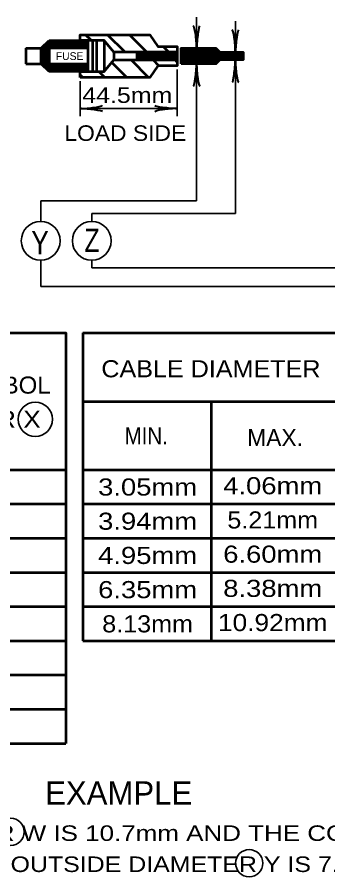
# Model space of a CAD drawing. Extents: x -32 to 824, y -6 to 538.
# Drawn here: x 393.4 to 441.4, y 267.8 to 400.5 of the extents above; entities that cross this region are included whole.
import ezdxf
from ezdxf.enums import TextEntityAlignment as Align

# ---------------------------------------------------------------- set-up
doc = ezdxf.new("R2010")
doc.units = 0
doc.header["$LTSCALE"] = 1.1
doc.layers.add('1', color=7, linetype='Continuous', lineweight=53)

msp = doc.modelspace()

# ---------------------------------------------------------------- linework, layer by layer
at = {"layer": '1', "lineweight": 35}
for p, q in [((421.085, 395.718), (421.085, 400.518)), ((427.085, 395.118), (427.085, 399.918)), ((421.085, 393.318), (421.085, 372.168)), ((427.085, 393.918), (427.085, 370.218)), ((418.085, 392.418), (418.085, 385.218)), ((403.085, 390.618), (403.085, 385.218)), ((403.085, 386.418), (418.085, 386.418)), ((421.085, 372.168), (396.989, 372.168)), ((396.989, 372.168), (396.989, 369.001)), ((427.085, 370.218), (404.885, 370.218)), ((404.885, 370.218), (404.885, 369.001)), ((396.989, 363.001), (396.989, 358.968)), ((404.885, 363.001), (404.885, 361.818)), ((404.885, 361.818), (511.085, 361.818)), ((396.989, 358.968), (448.542, 358.968))]:
    msp.add_line(p, q, dxfattribs=at)
at = {"layer": '1'}
for p, q in [((397.085, 395.718), (398.285, 396.918)), ((397.085, 395.687), (398.317, 396.918)), ((397.085, 395.517), (398.486, 396.918)), ((397.085, 395.347), (398.656, 396.918)), ((397.085, 395.178), (398.826, 396.918)), ((397.085, 395.008), (398.995, 396.918)), ((397.085, 394.838), (399.165, 396.918)), ((397.085, 394.668), (399.335, 396.918)), ((399.318, 395.718), (398.202, 396.834)), ((398.285, 396.918), (403.085, 396.918)), ((399.487, 395.718), (398.287, 396.918)), ((398.305, 395.718), (399.505, 396.918)), ((399.657, 395.718), (398.457, 396.918)), ((398.474, 395.718), (399.674, 396.918)), ((399.827, 395.718), (398.627, 396.918)), ((398.644, 395.718), (399.844, 396.918)), ((399.997, 395.718), (398.797, 396.918)), ((398.814, 395.718), (400.014, 396.918)), ((400.166, 395.718), (398.966, 396.918)), ((398.983, 395.718), (400.183, 396.918)), ((400.336, 395.718), (399.136, 396.918)), ((399.153, 395.718), (400.353, 396.918)), ((400.506, 395.718), (399.306, 396.918)), ((399.323, 395.718), (400.523, 396.918)), ((400.675, 395.718), (399.475, 396.918)), ((399.493, 395.718), (400.692, 396.918)), ((400.845, 395.718), (399.645, 396.918)), ((399.662, 395.718), (400.862, 396.918)), ((401.015, 395.718), (399.815, 396.918)), ((399.832, 395.718), (401.032, 396.918)), ((401.185, 395.718), (399.985, 396.918)), ((400.002, 395.718), (401.202, 396.918)), ((401.354, 395.718), (400.154, 396.918)), ((400.171, 395.718), (401.371, 396.918)), ((401.524, 395.718), (400.324, 396.918)), ((400.341, 395.718), (401.541, 396.918)), ((401.694, 395.718), (400.494, 396.918)), ((400.511, 395.718), (401.711, 396.918)), ((401.863, 395.718), (400.663, 396.918)), ((400.68, 395.718), (401.88, 396.918)), ((402.033, 395.718), (400.833, 396.918)), ((400.85, 395.718), (402.05, 396.918)), ((402.203, 395.718), (401.003, 396.918)), ((401.02, 395.718), (402.22, 396.918)), ((402.372, 395.718), (401.172, 396.918)), ((401.19, 395.718), (402.389, 396.918)), ((402.542, 395.718), (401.342, 396.918)), ((401.359, 395.718), (402.559, 396.918)), ((402.712, 395.718), (401.512, 396.918)), ((401.529, 395.718), (402.729, 396.918)), ((402.882, 395.718), (401.682, 396.918)), ((401.699, 395.718), (402.899, 396.918)), ((403.051, 395.718), (401.851, 396.918)), ((401.868, 395.718), (403.068, 396.918)), ((403.221, 395.718), (402.021, 396.918)), ((402.038, 395.718), (403.238, 396.918)), ((403.391, 395.718), (402.191, 396.918)), ((402.208, 395.718), (403.408, 396.918)), ((403.56, 395.718), (402.36, 396.918)), ((402.377, 395.718), (403.577, 396.918)), ((403.73, 395.718), (402.53, 396.918)), ((402.547, 395.718), (403.747, 396.918)), ((403.9, 395.718), (402.7, 396.918)), ((402.717, 395.718), (403.917, 396.918)), ((404.069, 395.718), (402.869, 396.918)), ((402.887, 395.718), (404.087, 396.918)), ((404.239, 395.718), (403.039, 396.918)), ((403.056, 395.718), (404.256, 396.918)), ((404.285, 395.841), (403.209, 396.918)), ((403.226, 395.718), (404.285, 396.777)), ((404.285, 396.011), (403.379, 396.918)), ((404.285, 396.181), (403.548, 396.918)), ((404.285, 396.351), (403.718, 396.918)), ((404.285, 396.52), (403.888, 396.918)), ((404.83, 396.918), (403.93, 397.818)), ((404.285, 396.69), (404.057, 396.918)), ((404.285, 396.86), (404.227, 396.918)), ((405.005, 396.918), (405.005, 392.118)), ((405.605, 396.918), (405.605, 392.118)), ((406.805, 396.918), (406.805, 392.118)), ((410.024, 395.118), (407.324, 397.818)), ((413.418, 395.118), (410.719, 397.818)), ((394.685, 395.718), (394.685, 393.318)), ((394.685, 395.718), (397.085, 395.718)), ((397.085, 394.499), (398.285, 395.699)), ((398.285, 394.374), (397.085, 395.574)), ((397.085, 394.329), (398.285, 395.529)), ((398.285, 394.544), (397.099, 395.731)), ((398.285, 394.714), (397.183, 395.816)), ((398.285, 394.883), (397.268, 395.901)), ((398.285, 395.053), (397.353, 395.986)), ((398.285, 395.223), (397.438, 396.07)), ((398.285, 395.393), (397.523, 396.155)), ((398.285, 395.562), (397.608, 396.24)), ((398.3, 395.718), (397.692, 396.325)), ((398.469, 395.718), (397.777, 396.41)), ((398.639, 395.718), (397.862, 396.495)), ((398.809, 395.718), (397.947, 396.579)), ((398.978, 395.718), (398.032, 396.664)), ((399.148, 395.718), (398.117, 396.749)), ((403.396, 395.718), (404.285, 396.608)), ((403.565, 395.718), (404.285, 396.438)), ((403.735, 395.718), (404.285, 396.268)), ((403.905, 395.718), (404.285, 396.099)), ((404.075, 395.718), (404.285, 395.929)), ((404.244, 395.718), (404.285, 395.759)), ((404.285, 395.718), (404.285, 393.318)), ((416.813, 395.118), (415.913, 396.018)), ((418.685, 395.591), (418.813, 395.718)), ((418.685, 395.421), (418.983, 395.718)), ((418.685, 395.251), (419.152, 395.718)), ((418.685, 395.081), (419.322, 395.718)), ((418.685, 394.912), (419.492, 395.718)), ((418.685, 394.742), (419.661, 395.718)), ((418.685, 394.572), (419.831, 395.718)), ((418.685, 394.403), (420.001, 395.718)), ((418.685, 394.233), (420.171, 395.718)), ((418.685, 394.063), (420.34, 395.718)), ((418.685, 393.893), (420.51, 395.718)), ((418.685, 393.724), (420.68, 395.718)), ((418.685, 393.554), (420.849, 395.718)), ((418.685, 393.384), (421.019, 395.718)), ((420.933, 393.318), (418.685, 395.565)), ((421.103, 393.318), (418.703, 395.718)), ((418.789, 393.318), (421.189, 395.718)), ((421.272, 393.318), (418.872, 395.718)), ((418.958, 393.318), (421.358, 395.718)), ((421.442, 393.318), (419.042, 395.718)), ((419.128, 393.318), (421.528, 395.718)), ((421.612, 393.318), (419.212, 395.718)), ((419.298, 393.318), (421.698, 395.718)), ((421.781, 393.318), (419.381, 395.718)), ((419.468, 393.318), (421.868, 395.718)), ((421.951, 393.318), (419.551, 395.718)), ((419.637, 393.318), (422.037, 395.718)), ((422.121, 393.318), (419.721, 395.718)), ((419.807, 393.318), (422.207, 395.718)), ((422.29, 393.318), (419.89, 395.718)), ((419.977, 393.318), (422.377, 395.718)), ((422.46, 393.318), (420.06, 395.718)), ((420.146, 393.318), (422.546, 395.718)), ((422.63, 393.318), (420.23, 395.718)), ((420.316, 393.318), (422.716, 395.718)), ((422.8, 393.318), (420.4, 395.718)), ((420.486, 393.318), (422.886, 395.718)), ((422.969, 393.318), (420.569, 395.718)), ((420.656, 393.318), (423.055, 395.718)), ((423.139, 393.318), (420.739, 395.718)), ((420.825, 393.318), (423.225, 395.718)), ((423.309, 393.318), (420.909, 395.718)), ((420.995, 393.318), (423.395, 395.718)), ((423.478, 393.318), (421.078, 395.718)), ((421.165, 393.318), (423.565, 395.718)), ((423.648, 393.318), (421.248, 395.718)), ((421.334, 393.318), (423.734, 395.718)), ((423.818, 393.318), (421.418, 395.718)), ((421.504, 393.318), (423.904, 395.718)), ((423.988, 393.318), (421.588, 395.718)), ((421.674, 393.318), (424.074, 395.718)), ((424.121, 393.354), (421.757, 395.718)), ((421.843, 393.318), (424.164, 395.639)), ((424.206, 393.439), (421.927, 395.718)), ((422.013, 393.318), (424.249, 395.554)), ((424.291, 393.524), (422.097, 395.718)), ((422.183, 393.318), (424.334, 395.469)), ((424.376, 393.608), (422.266, 395.718)), ((424.461, 393.693), (422.436, 395.718)), ((424.546, 393.778), (422.606, 395.718)), ((424.63, 393.863), (422.775, 395.718)), ((424.745, 393.918), (422.945, 395.718)), ((424.915, 393.918), (423.115, 395.718)), ((425.085, 393.918), (423.285, 395.718)), ((425.254, 393.918), (423.454, 395.718)), ((425.424, 393.918), (423.624, 395.718)), ((425.594, 393.918), (423.794, 395.718)), ((425.763, 393.918), (423.963, 395.718)), ((398.285, 394.205), (397.085, 395.405)), ((397.085, 394.159), (398.285, 395.359)), ((398.285, 394.035), (397.085, 395.235)), ((397.085, 393.99), (398.285, 395.19)), ((398.285, 393.865), (397.085, 395.065)), ((397.085, 393.82), (398.285, 395.02)), ((398.285, 393.696), (397.085, 394.896)), ((397.085, 393.65), (398.285, 394.85)), ((398.285, 393.526), (397.085, 394.726)), ((397.085, 393.481), (398.285, 394.681)), ((398.285, 393.356), (397.085, 394.556)), ((399.354, 392.118), (397.085, 394.386)), ((399.184, 392.118), (397.085, 394.217)), ((397.089, 393.314), (398.285, 394.511)), ((397.174, 393.23), (398.285, 394.341)), ((397.259, 393.145), (398.285, 394.171)), ((408.305, 395.118), (408.305, 393.918)), ((411.905, 394.992), (412.031, 395.118)), ((411.905, 394.822), (412.201, 395.118)), ((411.905, 394.653), (412.371, 395.118)), ((411.905, 394.483), (412.541, 395.118)), ((411.905, 394.313), (412.71, 395.118)), ((411.905, 394.143), (412.88, 395.118)), ((411.905, 393.974), (413.05, 395.118)), ((412.946, 393.918), (411.905, 394.958)), ((412.776, 393.918), (411.905, 394.788)), ((412.606, 393.918), (411.905, 394.619)), ((412.437, 393.918), (411.905, 394.449)), ((412.267, 393.918), (411.905, 394.279)), ((412.097, 393.918), (411.905, 394.11)), ((413.115, 393.918), (411.915, 395.118)), ((412.019, 393.918), (413.219, 395.118)), ((413.285, 393.918), (412.085, 395.118)), ((412.189, 393.918), (413.389, 395.118)), ((413.455, 393.918), (412.255, 395.118)), ((412.359, 393.918), (413.559, 395.118)), ((413.625, 393.918), (412.425, 395.118)), ((412.529, 393.918), (413.728, 395.118)), ((413.794, 393.918), (412.594, 395.118)), ((412.698, 393.918), (413.898, 395.118)), ((413.964, 393.918), (412.764, 395.118)), ((412.868, 393.918), (414.068, 395.118)), ((414.134, 393.918), (412.934, 395.118)), ((413.038, 393.918), (414.238, 395.118)), ((414.303, 393.918), (413.103, 395.118)), ((413.207, 393.918), (414.407, 395.118)), ((414.473, 393.918), (413.273, 395.118)), ((413.377, 393.918), (414.577, 395.118)), ((414.643, 393.918), (413.443, 395.118)), ((413.547, 393.918), (414.747, 395.118)), ((414.812, 393.918), (413.612, 395.118)), ((413.716, 393.918), (414.916, 395.118)), ((414.982, 393.918), (413.782, 395.118)), ((413.886, 393.918), (415.086, 395.118)), ((415.152, 393.918), (413.952, 395.118)), ((414.056, 393.918), (415.256, 395.118)), ((415.322, 393.918), (414.122, 395.118)), ((414.226, 393.918), (415.425, 395.118)), ((415.491, 393.918), (414.291, 395.118)), ((414.395, 393.918), (415.595, 395.118)), ((415.661, 393.918), (414.461, 395.118)), ((414.565, 393.918), (415.765, 395.118)), ((415.831, 393.918), (414.631, 395.118)), ((414.735, 393.918), (415.935, 395.118)), ((416, 393.918), (414.8, 395.118)), ((414.904, 393.918), (416.104, 395.118)), ((416.17, 393.918), (414.97, 395.118)), ((415.074, 393.918), (416.274, 395.118)), ((416.34, 393.918), (415.14, 395.118)), ((415.244, 393.918), (416.444, 395.118)), ((416.51, 393.918), (415.31, 395.118)), ((415.413, 393.918), (416.614, 395.118)), ((416.679, 393.918), (415.479, 395.118)), ((415.583, 393.918), (416.783, 395.118)), ((416.849, 393.918), (415.649, 395.118)), ((415.753, 393.918), (416.953, 395.118)), ((417.019, 393.918), (415.819, 395.118)), ((415.923, 393.918), (417.123, 395.118)), ((417.188, 393.918), (415.988, 395.118)), ((416.092, 393.918), (417.292, 395.118)), ((417.358, 393.918), (416.158, 395.118)), ((416.262, 393.918), (417.462, 395.118)), ((417.528, 393.918), (416.328, 395.118)), ((416.432, 393.918), (417.632, 395.118)), ((417.697, 393.918), (416.497, 395.118)), ((416.601, 393.918), (417.801, 395.118)), ((417.867, 393.918), (416.667, 395.118)), ((416.771, 393.918), (417.971, 395.118)), ((418.037, 393.918), (416.837, 395.118)), ((416.941, 393.918), (418.085, 395.062)), ((418.085, 394.039), (417.007, 395.118)), ((417.111, 393.918), (418.085, 394.893)), ((418.085, 394.209), (417.176, 395.118)), ((417.28, 393.918), (418.085, 394.723)), ((418.085, 394.379), (417.346, 395.118)), ((417.45, 393.918), (418.085, 394.553)), ((418.085, 394.548), (417.516, 395.118)), ((417.62, 393.918), (418.085, 394.384)), ((418.085, 394.718), (417.685, 395.118)), ((417.789, 393.918), (418.085, 394.214)), ((418.085, 394.888), (417.855, 395.118)), ((418.085, 395.057), (418.025, 395.118)), ((420.763, 393.318), (418.685, 395.396)), ((420.593, 393.318), (418.685, 395.226)), ((420.424, 393.318), (418.685, 395.056)), ((420.254, 393.318), (418.685, 394.886)), ((420.084, 393.318), (418.685, 394.717)), ((419.915, 393.318), (418.685, 394.547)), ((419.745, 393.318), (418.685, 394.377)), ((419.575, 393.318), (418.685, 394.208)), ((422.353, 393.318), (424.419, 395.384)), ((422.522, 393.318), (424.504, 395.3)), ((422.692, 393.318), (424.589, 395.215)), ((422.862, 393.318), (424.674, 395.13)), ((423.031, 393.318), (424.831, 395.118)), ((423.201, 393.318), (425.001, 395.118)), ((423.371, 393.318), (425.171, 395.118)), ((423.541, 393.318), (425.341, 395.118)), ((423.71, 393.318), (425.51, 395.118)), ((423.88, 393.318), (425.68, 395.118)), ((424.05, 393.318), (425.85, 395.118)), ((425.933, 393.918), (424.733, 395.118)), ((424.819, 393.918), (426.019, 395.118)), ((426.103, 393.918), (424.903, 395.118)), ((424.989, 393.918), (426.189, 395.118)), ((426.273, 393.918), (425.073, 395.118)), ((425.159, 393.918), (426.359, 395.118)), ((426.442, 393.918), (425.242, 395.118)), ((425.328, 393.918), (426.528, 395.118)), ((426.612, 393.918), (425.412, 395.118)), ((425.498, 393.918), (426.698, 395.118)), ((426.782, 393.918), (425.582, 395.118)), ((425.668, 393.918), (426.868, 395.118)), ((426.951, 393.918), (425.751, 395.118)), ((425.838, 393.918), (427.038, 395.118)), ((427.121, 393.918), (425.921, 395.118)), ((426.007, 393.918), (427.207, 395.118)), ((427.291, 393.918), (426.091, 395.118)), ((426.177, 393.918), (427.377, 395.118)), ((427.46, 393.918), (426.26, 395.118)), ((426.347, 393.918), (427.547, 395.118)), ((427.63, 393.918), (426.43, 395.118)), ((426.516, 393.918), (427.716, 395.118)), ((427.8, 393.918), (426.6, 395.118)), ((426.686, 393.918), (427.886, 395.118)), ((427.97, 393.918), (426.769, 395.118)), ((426.856, 393.918), (428.056, 395.118)), ((428.139, 393.918), (426.939, 395.118)), ((427.026, 393.918), (428.226, 395.118)), ((428.285, 393.941), (427.109, 395.118)), ((427.195, 393.918), (428.285, 395.008)), ((428.285, 394.111), (427.279, 395.118)), ((427.365, 393.918), (428.285, 394.838)), ((428.285, 394.281), (427.448, 395.118)), ((427.535, 393.918), (428.285, 394.669)), ((428.285, 394.451), (427.618, 395.118)), ((427.704, 393.918), (428.285, 394.499)), ((428.285, 394.62), (427.788, 395.118)), ((427.874, 393.918), (428.285, 394.329)), ((428.285, 394.79), (427.958, 395.118)), ((428.044, 393.918), (428.285, 394.16)), ((428.285, 394.96), (428.127, 395.118)), ((394.685, 393.318), (397.085, 393.318)), ((399.014, 392.118), (397.085, 394.047)), ((398.845, 392.118), (397.085, 393.877)), ((398.675, 392.118), (397.085, 393.708)), ((398.505, 392.118), (397.085, 393.538)), ((398.336, 392.118), (397.085, 393.368)), ((397.344, 393.06), (398.285, 394.002)), ((397.428, 392.975), (398.285, 393.832)), ((397.513, 392.89), (398.285, 393.662)), ((397.598, 392.805), (398.285, 393.493)), ((397.683, 392.72), (398.285, 393.323)), ((397.768, 392.636), (398.45, 393.318)), ((397.853, 392.551), (398.62, 393.318)), ((397.938, 392.466), (398.79, 393.318)), ((398.022, 392.381), (398.959, 393.318)), ((398.107, 392.296), (399.129, 393.318)), ((398.192, 392.211), (399.299, 393.318)), ((398.277, 392.126), (399.468, 393.318)), ((399.524, 392.118), (398.324, 393.318)), ((398.438, 392.118), (399.638, 393.318)), ((399.693, 392.118), (398.493, 393.318)), ((398.608, 392.118), (399.808, 393.318)), ((399.863, 392.118), (398.663, 393.318)), ((398.777, 392.118), (399.977, 393.318)), ((400.033, 392.118), (398.833, 393.318)), ((398.947, 392.118), (400.147, 393.318)), ((400.202, 392.118), (399.002, 393.318)), ((399.117, 392.118), (400.317, 393.318)), ((400.372, 392.118), (399.172, 393.318)), ((399.287, 392.118), (400.487, 393.318)), ((400.542, 392.118), (399.342, 393.318)), ((399.456, 392.118), (400.656, 393.318)), ((400.712, 392.118), (399.512, 393.318)), ((399.626, 392.118), (400.826, 393.318)), ((400.881, 392.118), (399.681, 393.318)), ((399.796, 392.118), (400.996, 393.318)), ((401.051, 392.118), (399.851, 393.318)), ((399.965, 392.118), (401.165, 393.318)), ((401.221, 392.118), (400.021, 393.318)), ((400.135, 392.118), (401.335, 393.318)), ((401.39, 392.118), (400.19, 393.318)), ((400.305, 392.118), (401.505, 393.318)), ((401.56, 392.118), (400.36, 393.318)), ((400.475, 392.118), (401.675, 393.318)), ((401.73, 392.118), (400.53, 393.318)), ((400.644, 392.118), (401.844, 393.318)), ((401.9, 392.118), (400.7, 393.318)), ((400.814, 392.118), (402.014, 393.318)), ((402.069, 392.118), (400.869, 393.318)), ((400.984, 392.118), (402.184, 393.318)), ((402.239, 392.118), (401.039, 393.318)), ((401.153, 392.118), (402.353, 393.318)), ((402.409, 392.118), (401.209, 393.318)), ((401.323, 392.118), (402.523, 393.318)), ((402.578, 392.118), (401.378, 393.318)), ((401.493, 392.118), (402.693, 393.318)), ((402.748, 392.118), (401.548, 393.318)), ((401.662, 392.118), (402.862, 393.318)), ((402.918, 392.118), (401.718, 393.318)), ((401.832, 392.118), (403.032, 393.318)), ((403.087, 392.118), (401.887, 393.318)), ((402.002, 392.118), (403.202, 393.318)), ((403.257, 392.118), (402.057, 393.318)), ((402.172, 392.118), (403.372, 393.318)), ((403.427, 392.118), (402.227, 393.318)), ((402.341, 392.118), (403.541, 393.318)), ((403.596, 392.118), (402.397, 393.318)), ((402.511, 392.118), (403.711, 393.318)), ((403.766, 392.118), (402.566, 393.318)), ((402.681, 392.118), (403.881, 393.318)), ((403.936, 392.118), (402.736, 393.318)), ((402.85, 392.118), (404.05, 393.318)), ((404.106, 392.118), (402.906, 393.318)), ((403.02, 392.118), (404.22, 393.318)), ((404.275, 392.118), (403.075, 393.318)), ((403.19, 392.118), (404.285, 393.214)), ((404.285, 392.278), (403.245, 393.318)), ((403.36, 392.118), (404.285, 393.044)), ((404.285, 392.447), (403.415, 393.318)), ((403.529, 392.118), (404.285, 392.874)), ((404.285, 392.617), (403.584, 393.318)), ((404.285, 392.787), (403.754, 393.318)), ((404.285, 392.956), (403.924, 393.318)), ((404.285, 393.126), (404.094, 393.318)), ((404.285, 393.296), (404.263, 393.318)), ((410.283, 391.218), (407.977, 393.524)), ((413.677, 391.218), (410.977, 393.918)), ((411.927, 393.918), (411.905, 393.94)), ((415.271, 393.018), (414.371, 393.918)), ((418.085, 393.598), (417.765, 393.918)), ((417.959, 393.918), (418.085, 394.044)), ((419.405, 393.318), (418.685, 394.038)), ((419.236, 393.318), (418.685, 393.868)), ((419.066, 393.318), (418.685, 393.699)), ((418.896, 393.318), (418.685, 393.529)), ((418.727, 393.318), (418.685, 393.359)), ((428.213, 393.918), (428.285, 393.99)), ((403.085, 392.118), (398.285, 392.118)), ((403.495, 391.218), (403.085, 391.627)), ((403.699, 392.118), (404.285, 392.704)), ((403.869, 392.118), (404.285, 392.535)), ((404.038, 392.118), (404.285, 392.365)), ((404.208, 392.118), (404.285, 392.195)), ((406.889, 391.218), (405.989, 392.118)), ((403.515, 351.778), (403.515, 304.258)), ((403.515, 341.218), (443.115, 341.218)), ((423.315, 341.218), (423.315, 304.258)), ((341.475, 330.658), (400.875, 330.658)), ((403.515, 330.658), (462.915, 330.658)), ((341.475, 325.378), (400.875, 325.378)), ((403.515, 325.378), (462.915, 325.378)), ((341.475, 320.098), (400.875, 320.098)), ((403.515, 320.098), (462.915, 320.098)), ((341.475, 314.818), (400.875, 314.818)), ((403.515, 314.818), (462.915, 314.818)), ((341.475, 309.538), (400.875, 309.538)), ((403.515, 309.538), (462.915, 309.538)), ((341.475, 304.258), (400.875, 304.258)), ((403.515, 304.258), (462.915, 304.258)), ((341.475, 298.978), (400.875, 298.978)), ((341.475, 293.698), (400.875, 293.698)), ((341.475, 288.418), (400.875, 288.418))]:
    msp.add_line(p, q, dxfattribs=at)
for points in [[(404.285, 396.918), (404.285, 395.718), (398.285, 395.718), (398.285, 393.318), (404.285, 393.318), (404.285, 392.118)], [(398.285, 392.118), (397.085, 393.318), (397.085, 395.718)], [(341.475, 351.778), (400.875, 351.778), (400.875, 288.418)], [(403.515, 351.778), (462.915, 351.778), (462.915, 304.258)]]:
    msp.add_lwpolyline(points, dxfattribs=at)
for points in [[(403.085, 396.918), (403.085, 397.818), (413.885, 397.818), (415.085, 396.018), (418.085, 396.018), (418.085, 395.118), (411.905, 395.118), (408.305, 395.118), (406.805, 396.918)], [(418.685, 393.318), (418.685, 395.718), (424.085, 395.718), (424.685, 395.118), (428.285, 395.118), (428.285, 393.918), (424.685, 393.918), (424.085, 393.318)], [(411.905, 393.918), (411.905, 395.118), (418.085, 395.118), (418.085, 393.918)], [(403.085, 391.218), (403.085, 392.118), (406.805, 392.118), (408.305, 393.918), (411.905, 393.918), (418.085, 393.918), (418.085, 393.018), (415.085, 393.018), (413.885, 391.218)]]:
    msp.add_lwpolyline(points, close=True, dxfattribs=at)
at = {"layer": '1', "lineweight": 35}
for centre, radius in [((396.989, 366.001), 3), ((404.885, 366.001), 3), ((396.153, 338.451), 2.64), ((392.342, 274.764), 2.1), ((429.224, 269.923), 2.1)]:
    msp.add_circle(centre, radius, dxfattribs=at)
at = {"layer": '1', "lineweight": 40}
for centre, major_axis, ratio, start_param, end_param in [((420.754, 397.027), (0.187, -2.143), 0.122415, 0.8963533, 3.1415927), ((420.754, 397.027), (0.187, -2.143), 0.122415, 0.8963533, 3.1415927), ((421.339, 397.063), (-0.211, -2.108), 0.07063, 3.1407148, 5.41811), ((421.339, 397.063), (-0.211, -2.108), 0.07063, 3.1407148, 5.41811), ((426.754, 396.427), (0.187, -2.143), 0.122415, 0.8963533, 3.1415927), ((426.754, 396.427), (0.187, -2.143), 0.122415, 0.8963533, 3.1415927), ((427.339, 396.463), (-0.211, -2.108), 0.07063, 3.1407148, 5.41811), ((427.339, 396.463), (-0.211, -2.108), 0.07063, 3.1407148, 5.41811), ((420.831, 391.973), (0.211, 2.108), 0.07063, 3.1407148, 5.41811), ((420.831, 391.973), (0.211, 2.108), 0.07063, 3.1407148, 5.41811), ((421.417, 392.008), (-0.187, 2.143), 0.122415, 0.8963533, 3.1415927), ((421.417, 392.008), (-0.187, 2.143), 0.122415, 0.8963533, 3.1415927), ((426.831, 392.573), (0.211, 2.108), 0.07063, 3.1407148, 5.41811), ((427.417, 392.608), (-0.187, 2.143), 0.122415, 0.8963533, 3.1415927), ((404.43, 386.164), (-2.108, 0.211), 0.07063, 3.1407148, 5.41811), ((404.395, 386.749), (-2.143, -0.187), 0.122415, 0.8963533, 3.1415927), ((416.776, 386.086), (2.143, 0.187), 0.122415, 0.8963533, 3.1415927), ((416.741, 386.672), (2.108, -0.211), 0.07063, 3.1407148, 5.41811)]:
    msp.add_ellipse(centre, major_axis=major_axis, ratio=ratio, start_param=start_param, end_param=end_param, dxfattribs=at)

# ---------------------------------------------------------------- texts
at = {"layer": '1'}
for s, height, p in [('FUSE', 1.2, (399.32, 393.91)), ('MAX.', 2.64, (428.905, 334.301)), ('EXAMPLE', 3.6, (397.674, 278.968))]:
    msp.add_text(s, height=height, dxfattribs=at).set_placement(p)
for s, height, width, p in [('44.5mm', 2.4, 1.2, (403.42, 387.28)), ('LOAD SIDE', 2.4, 1.1, (400.647, 381.426)), ('Z', 3.6, 0.8, (403.745, 364.264)), ('Y', 3.6, 0.85, (395.529, 363.936)), ('CABLE DIAMETER', 2.64, 1.1, (406.363, 344.93)), ('MIN.', 2.64, 0.9, (409.952, 334.589)), ('IF THE LINE OUTSIDE DIAMETER W IS 10.7mm AND THE CONDUCTOR X IS 17.42mm2', 2.4, 1.25, (329.421, 273.363)), ('STRANDED, AND THE LOAD SIDE OUTSIDE DIAMETER Y IS 7.4mm AND THE CONDUC-', 2.4, 1.2, (329.421, 268.563))]:
    msp.add_text(s, height=height, dxfattribs=dict(at, width=width)).set_placement(p)
for s, width, p in [('SYMBOL', 1.05, (390.802, 342.41)), ('FOR X', 1.15, (390.802, 337.13)), ('3.05mm', 1.2, (413.517, 326.675)), ('4.06mm', 1.2, (432.853, 326.871)), ('3.94mm', 1.2, (413.517, 321.395)), ('5.21mm', 1.1, (432.853, 321.591)), ('4.95mm', 1.2, (413.517, 316.115)), ('6.60mm', 1.2, (432.853, 316.311)), ('6.35mm', 1.2, (413.517, 310.835)), ('8.38mm', 1.2, (432.853, 311.031)), ('8.13mm', 1.1, (413.517, 305.555)), ('10.92mm', 1.15, (432.853, 305.751))]:
    msp.add_text(s, height=2.64, dxfattribs=dict(at, width=width)).set_placement(p, align=Align.CENTER)

doc.saveas('drawing.dxf')
